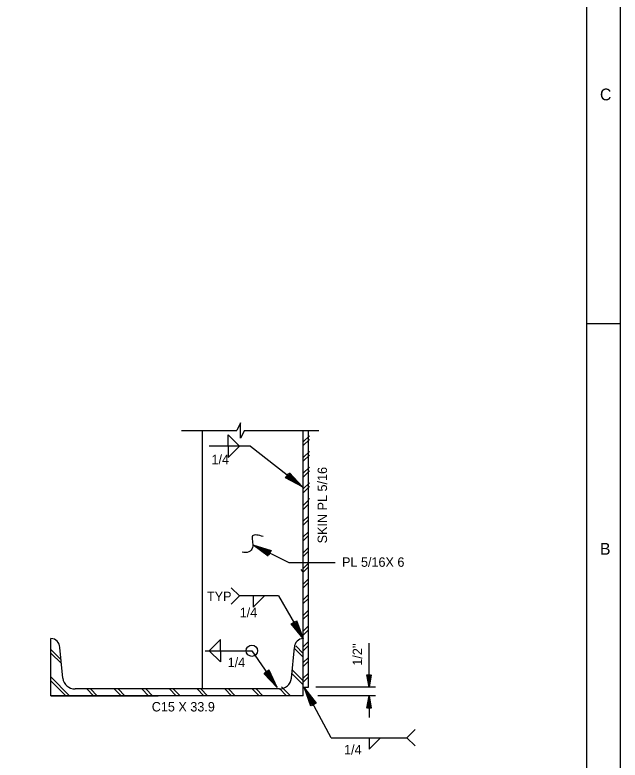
# Model space of a CAD drawing. Extents: x 0.1 to 13.5, y 0.1 to 9.5.
# Drawn here: x 10.461 to 13.458, y 2.629 to 6.319 of the extents above; entities that cross this region are included whole.
import ezdxf

# ---------------------------------------------------------------- set-up
doc = ezdxf.new("R2010")
doc.units = 0
for name, color, linetype in [('Level 1', 7, 'Continuous'), ('Level 13', 7, 'Continuous'), ('Level 25', 7, 'Continuous'), ('Level 3', 7, 'Continuous'), ('Level 44', 7, 'Continuous'), ('Level 50', 7, 'Continuous')]:
    doc.layers.add(name, color=color, linetype=linetype)

msp = doc.modelspace()

# ---------------------------------------------------------------- linework, layer by layer
at = {"layer": 'Level 1'}
for p, q in [((13.2917, 4.7917), (13.4583, 4.7917)), ((10.639, 2.9478), (10.639, 3.2311)), ((11.889, 2.9478), (11.889, 3.2311)), ((10.6394, 3.1561), (10.639, 3.1561)), ((11.8887, 3.1561), (11.889, 3.1561))]:
    msp.add_line(p, q, dxfattribs=at)
for points in [[(0.125, 9.4583), (13.4583, 9.4583), (13.4583, 0.125), (0.125, 0.125)], [(0.625, 9.2917), (13.2917, 9.2917), (13.2917, 0.2917), (0.625, 0.2917)]]:
    msp.add_lwpolyline(points, close=True, dxfattribs=at)
msp.add_spline([(11.6909, 3.7361), (11.6381, 3.7391), (11.637, 3.6811), (11.6194, 3.6599), (11.5856, 3.658)], degree=3, dxfattribs=at)
at = {"layer": 'Level 13'}
msp.add_lwpolyline([(11.5974, 4.2613), (11.5788, 4.2238), (11.5788, 4.2987), (11.56, 4.2613)], dxfattribs=at)
at = {"layer": 'Level 25'}
for p, q in [((11.2857, 4.2613), (11.56, 4.2613)), ((11.389, 2.9811), (11.389, 4.2613)), ((11.5974, 4.2613), (11.9664, 4.2613)), ((11.889, 2.9894), (11.889, 4.2613)), ((11.9151, 2.9894), (11.9151, 4.2613)), ((11.5164, 4.2389), (11.5723, 4.1831)), ((11.5164, 4.1827), (11.5164, 4.2389)), ((11.889, 4.2052), (11.9192, 4.2354)), ((11.889, 4.1864), (11.9192, 4.2165)), ((11.6276, 4.1833), (11.4224, 4.1833)), ((11.5164, 4.1839), (11.5164, 4.1276)), ((11.5164, 4.1276), (11.5723, 4.1835)), ((11.6276, 4.1833), (11.8844, 3.9818)), ((11.889, 4.1275), (11.9192, 4.1576)), ((11.889, 4.1086), (11.9192, 4.1387)), ((11.889, 4.0497), (11.9192, 4.0798)), ((11.889, 4.0308), (11.9192, 4.0609)), ((11.8639, 3.9978), (11.8639, 3.9978)), ((11.889, 3.9719), (11.9192, 4.002)), ((11.8844, 3.9818), (11.8844, 3.9818)), ((11.889, 3.953), (11.9192, 3.9831)), ((11.889, 3.8894), (11.9151, 3.9154)), ((11.913, 3.918), (11.9192, 3.9242)), ((11.889, 3.8705), (11.9151, 3.8966)), ((11.889, 3.8116), (11.9151, 3.8376)), ((11.889, 3.7927), (11.9151, 3.8188)), ((11.889, 3.7338), (11.9151, 3.7599)), ((11.889, 3.715), (11.9151, 3.741)), ((11.889, 3.656), (11.9151, 3.6821)), ((11.889, 3.6372), (11.9151, 3.6632)), ((11.889, 3.5783), (11.9151, 3.6043)), ((11.889, 3.5594), (11.9151, 3.5854)), ((11.889, 3.5619), (11.8786, 3.5724)), ((11.889, 3.5005), (11.9151, 3.5265)), ((11.889, 3.4816), (11.9151, 3.5077)), ((11.5724, 3.4417), (11.5326, 3.4816)), ((11.5724, 3.4417), (11.5326, 3.4019)), ((11.7662, 3.4417), (11.5724, 3.4417)), ((11.6415, 3.4423), (11.6415, 3.386)), ((11.6415, 3.386), (11.6974, 3.4419)), ((11.7662, 3.4417), (11.889, 3.2311)), ((11.889, 3.4227), (11.9151, 3.4487)), ((11.889, 3.4038), (11.9151, 3.4299)), ((11.889, 3.3449), (11.9151, 3.3709)), ((11.889, 3.3261), (11.9151, 3.3521)), ((11.889, 3.2671), (11.9151, 3.2932)), ((11.8759, 3.2536), (11.8759, 3.2536)), ((11.889, 3.2483), (11.9151, 3.2743)), ((11.479, 3.2262), (11.4231, 3.1704)), ((11.479, 3.17), (11.479, 3.2262)), ((11.889, 3.2311), (11.889, 3.2311)), ((11.889, 3.1893), (11.9151, 3.2154)), ((10.6974, 3.0344), (10.6833, 3.1867)), ((11.8306, 3.0344), (11.8448, 3.1867)), ((11.889, 3.1705), (11.9151, 3.1965)), ((12.2148, 2.9894), (12.2148, 3.2072)), ((11.4034, 3.1706), (11.6344, 3.1706)), ((11.479, 3.1149), (11.4231, 3.1708)), ((11.479, 3.1712), (11.479, 3.1149)), ((11.6344, 3.1706), (11.7596, 2.989)), ((11.889, 3.1116), (11.9151, 3.1376)), ((11.889, 3.0927), (11.9151, 3.1188)), ((11.889, 3.0338), (11.9151, 3.0598)), ((11.889, 3.0149), (11.9151, 3.041)), ((11.7449, 3.0104), (11.7449, 3.0104)), ((11.889, 2.9894), (11.9151, 2.9894)), ((12.2468, 2.9894), (11.9516, 2.9894)), ((11.7693, 2.9811), (10.7588, 2.9811)), ((11.7596, 2.989), (11.7596, 2.989)), ((12.0276, 2.7399), (11.895, 2.985)), ((11.895, 2.985), (11.895, 2.985)), ((11.9073, 2.9622), (11.9073, 2.9622)), ((11.889, 2.9478), (10.639, 2.9478)), ((12.2468, 2.9478), (11.9618, 2.9478)), ((12.2148, 2.9478), (12.2148, 2.8396)), ((12.4027, 2.7399), (12.4426, 2.7798)), ((12.0276, 2.7399), (12.4027, 2.7399)), ((12.2151, 2.7399), (12.2151, 2.6837)), ((12.2151, 2.6837), (12.271, 2.7396)), ((12.4027, 2.7399), (12.4426, 2.7002))]:
    msp.add_line(p, q, dxfattribs=at)
for points in [[(11.8204, 4.0517), (11.8844, 3.9818), (11.8013, 4.0273), (11.8176, 4.0481), (11.8639, 3.9978), (11.8075, 4.0288), (11.818, 4.0421), (11.8443, 4.0132), (11.8137, 4.0302), (11.818, 4.0357), (11.8238, 4.0293)], [(11.8553, 3.3197), (11.889, 3.2311), (11.8286, 3.3041), (11.8514, 3.3174), (11.8759, 3.2536), (11.8349, 3.3031), (11.8496, 3.3117), (11.8633, 3.2752), (11.8412, 3.3022), (11.8473, 3.3057), (11.8503, 3.2976)], [(11.6938, 3.0572), (11.7596, 2.989), (11.7193, 3.0748), (11.6975, 3.0597), (11.7449, 3.0104), (11.7175, 3.0686), (11.7035, 3.059), (11.7307, 3.031), (11.7156, 3.0625), (11.7099, 3.0585), (11.7159, 3.0524)], [(11.9258, 2.8954), (11.895, 2.985), (11.9531, 2.9102), (11.9298, 2.8976), (11.9073, 2.9622), (11.9468, 2.9113), (11.9319, 2.9032), (11.9192, 2.9402), (11.9405, 2.9125), (11.9343, 2.9091), (11.9316, 2.9173)]]:
    msp.add_lwpolyline(points, dxfattribs=at)
msp.add_circle((11.6344, 3.1706), 0.0281, dxfattribs=at)
for centre, radius, start, end in [((10.6376, 3.1855), 0.0457, 1.5529, 88.2316), ((11.8905, 3.1855), 0.0457, 91.7684, 178.4471), ((10.7583, 3.0425), 0.0614, 187.587, 270.4984), ((11.7698, 3.0425), 0.0614, 269.5016, 352.413)]:
    msp.add_arc(centre, radius, start, end, dxfattribs=at)
at = {"layer": 'Level 3'}
for p, q in [((11.6385, 3.6945), (11.6385, 3.6945)), ((11.6619, 3.6831), (11.6619, 3.6831))]:
    msp.add_line(p, q, dxfattribs=at)
for points in [[(12.0474, 3.6063), (11.8189, 3.6063), (11.6385, 3.6945)], [(11.7157, 3.6395), (11.6385, 3.6945), (11.7293, 3.6673), (11.7177, 3.6435), (11.6619, 3.6831), (11.7235, 3.6646), (11.7161, 3.6493), (11.6843, 3.6721), (11.7177, 3.6619), (11.7147, 3.6556), (11.7077, 3.6606)]]:
    msp.add_lwpolyline(points, dxfattribs=at)
at = {"layer": 'Level 44'}
for p, q in [((10.6888, 3.1273), (10.639, 3.1771)), ((11.889, 3.1386), (11.8445, 3.1831)), ((11.889, 3.1574), (11.8523, 3.1942)), ((10.6907, 3.1065), (10.639, 3.1582)), ((11.889, 3.0207), (11.8344, 3.0753)), ((10.7316, 2.9478), (10.639, 3.0404)), ((11.889, 3.0019), (11.8328, 3.0581)), ((10.7128, 2.9478), (10.639, 3.0215)), ((11.8253, 2.9478), (11.7814, 2.9917)), ((10.8495, 2.9478), (10.8161, 2.9811)), ((10.8683, 2.9478), (10.835, 2.9811)), ((10.9862, 2.9478), (10.9529, 2.9811)), ((11.005, 2.9478), (10.9717, 2.9811)), ((11.1229, 2.9478), (11.0896, 2.9811)), ((11.1418, 2.9478), (11.1084, 2.9811)), ((11.2596, 2.9478), (11.2263, 2.9811)), ((11.2785, 2.9478), (11.2451, 2.9811)), ((11.3963, 2.9478), (11.363, 2.9811)), ((11.4152, 2.9478), (11.3818, 2.9811)), ((11.533, 2.9478), (11.4997, 2.9811)), ((11.5519, 2.9478), (11.5185, 2.9811)), ((11.6697, 2.9478), (11.6364, 2.9811)), ((11.6886, 2.9478), (11.6553, 2.9811)), ((11.8064, 2.9478), (11.7713, 2.9829)), ((10.639, 2.9478), (11.1708, 2.9478))]:
    msp.add_line(p, q, dxfattribs=at)
at = {"layer": 'Level 50'}
for p, q in [((12.2148, 3.0068), (12.2148, 3.0068)), ((12.2148, 2.9894), (12.2148, 2.9894)), ((12.2148, 2.9478), (12.2148, 2.9478)), ((12.2148, 2.9304), (12.2148, 2.9304))]:
    msp.add_line(p, q, dxfattribs=at)
for points in [[(12.2252, 3.0518), (12.2148, 2.9894), (12.2045, 3.0518), (12.2222, 3.0518), (12.2148, 3.0068), (12.2078, 3.0491), (12.2192, 3.0491), (12.2148, 3.0234), (12.2112, 3.0464), (12.2158, 3.0464), (12.2148, 3.0408)], [(12.2045, 2.8854), (12.2148, 2.9478), (12.2252, 2.8854), (12.2075, 2.8854), (12.2148, 2.9304), (12.2218, 2.8881), (12.2105, 2.8881), (12.2148, 2.9138), (12.2185, 2.8908), (12.2138, 2.8908), (12.2148, 2.8964)]]:
    msp.add_lwpolyline(points, dxfattribs=at)

# ---------------------------------------------------------------- texts
at = {"layer": 'Level 1'}
for s, height, p in [('C', 0.0584, (13.3587, 5.8961)), ('B', 0.0584, (13.3587, 3.6461)), ('C15 X 33.9', 0.0467, (11.1385, 2.8697))]:
    msp.add_text(s, height=height, dxfattribs=at).set_placement(p)
at = {"layer": 'Level 25'}
for s, p in [('1/4', (11.4342, 4.0942)), ('PL 5/16X 6', (12.081, 3.5862)), ('TYP', (11.412, 3.4161)), ('1/4', (11.574, 3.3365)), ('1/4', (11.5144, 3.0897)), ('1/4', (12.0909, 2.6571))]:
    msp.add_text(s, height=0.0467, dxfattribs=at).set_placement(p)
for s, height, p in [('SKIN PL 5/16', 0.046698, (12.0067, 3.7022)), ("1/2''", 0.0467, (12.1806, 3.0963))]:
    msp.add_text(s, height=height, rotation=90, dxfattribs=at).set_placement(p)

doc.saveas('drawing.dxf')
